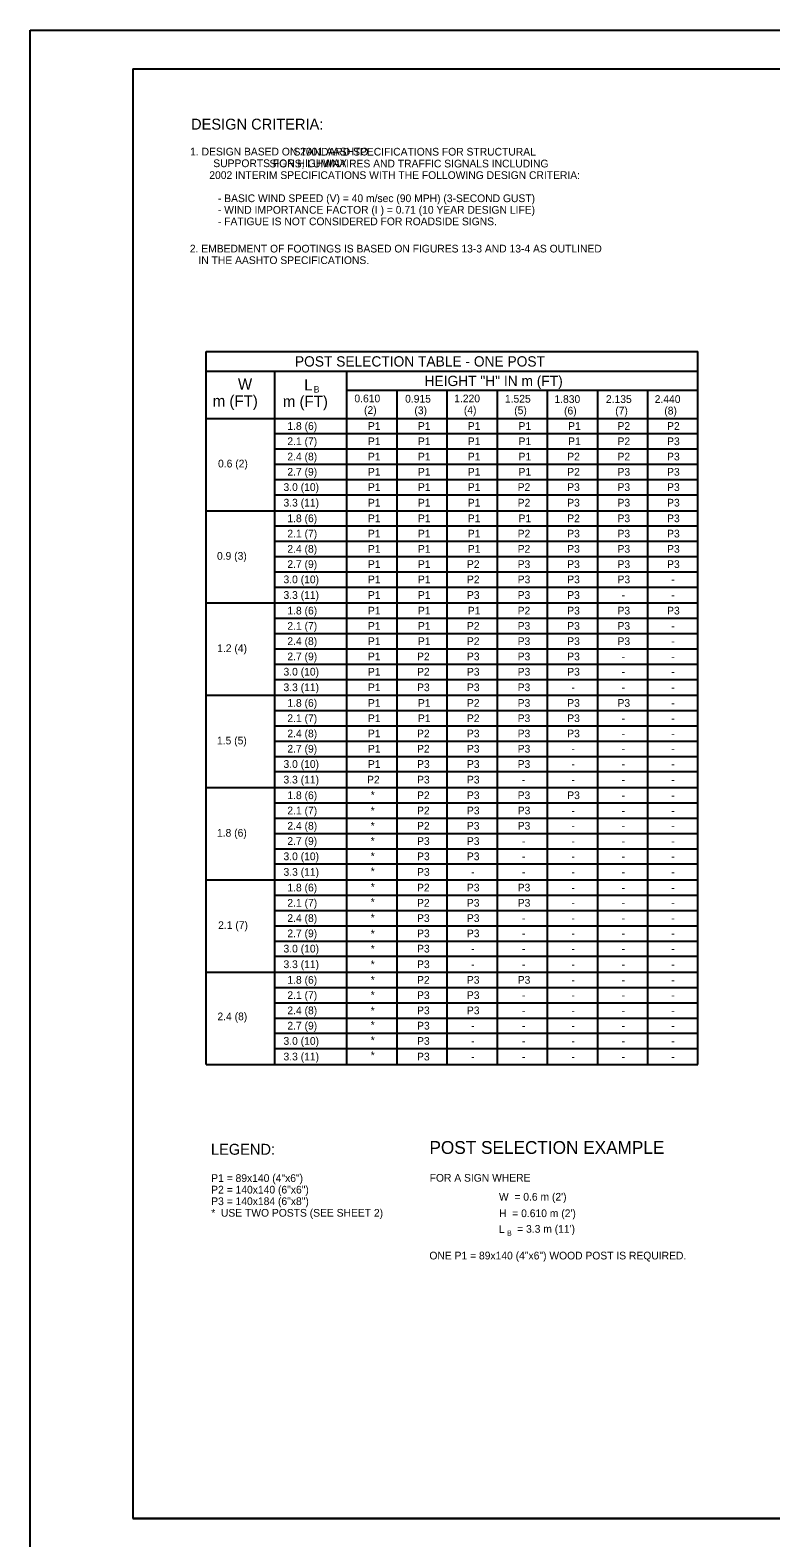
# Model space of a CAD drawing. Extents: x -1958 to 628, y -879 to 309.
# Drawn here: x -1958 to -1670, y -277 to 309 of the extents above; entities that cross this region are included whole.
import ezdxf

# ---------------------------------------------------------------- set-up
doc = ezdxf.new("R2010")
doc.units = 0
for name, color, linetype in [('1', 7, 'Continuous'), ('2', 7, 'Continuous'), ('3', 7, 'Continuous'), ('4', 7, 'Continuous'), ('PLT-BNDY', 7, 'Continuous')]:
    doc.layers.add(name, color=color, linetype=linetype)

msp = doc.modelspace()

# ---------------------------------------------------------------- linework, layer by layer
at = {"layer": '1'}
for p, q in [((-1918.39, 294.44), (-1132.39, 294.44)), ((-1918.39, 294.44), (-1918.39, -269.56)), ((-1889.94, 158.42), (-1889.94, 184.44)), ((-1889.94, 184.44), (-1698.58, 184.44)), ((-1698.58, -92.95), (-1698.58, 184.44)), ((-1889.94, 176.76), (-1835.13, 176.76)), ((-1863.14, -92.95), (-1863.14, 176.76)), ((-1835.13, -92.95), (-1835.13, 176.76)), ((-1835.13, 176.76), (-1698.58, 176.76)), ((-1815.62, 158.42), (-1815.62, 169.42)), ((-1796.12, 158.42), (-1796.12, 169.42)), ((-1776.61, 158.42), (-1776.61, 169.42)), ((-1757.1, 158.42), (-1757.1, 169.42)), ((-1737.59, 158.42), (-1737.59, 169.42)), ((-1718.09, 158.42), (-1718.09, 169.42)), ((-1889.94, 158.42), (-1698.58, 158.42)), ((-1132.39, -269.56), (-1918.39, -269.56)), ((-1918.39, -269.56), (-1332.39, -269.56))]:
    msp.add_line(p, q, dxfattribs=at)
at = {"layer": '2'}
for p, q in [((-1835.13, 169.42), (-1698.58, 169.42)), ((-1889.94, -92.95), (-1889.94, 158.42)), ((-1815.62, -92.95), (-1815.62, 158.42)), ((-1796.12, -92.95), (-1796.12, 158.42)), ((-1776.61, -92.95), (-1776.61, 158.42)), ((-1757.1, -92.95), (-1757.1, 158.42)), ((-1737.59, -92.95), (-1737.59, 158.42)), ((-1718.09, -92.95), (-1718.09, 158.42)), ((-1863.14, 152.48), (-1698.58, 152.48)), ((-1863.14, 146.54), (-1698.58, 146.54)), ((-1863.14, 140.6), (-1698.58, 140.6)), ((-1863.14, 134.66), (-1698.58, 134.66)), ((-1863.14, 128.72), (-1698.58, 128.72)), ((-1889.94, 122.51), (-1698.58, 122.51)), ((-1863.14, 116.57), (-1698.58, 116.57)), ((-1863.14, 110.63), (-1698.58, 110.63)), ((-1863.14, 104.69), (-1698.58, 104.69)), ((-1863.14, 98.75), (-1698.58, 98.75)), ((-1863.14, 92.81), (-1698.58, 92.81)), ((-1889.94, 86.6), (-1698.58, 86.6)), ((-1863.14, 80.66), (-1698.58, 80.66)), ((-1863.14, 74.72), (-1698.58, 74.72)), ((-1863.14, 68.78), (-1698.58, 68.78)), ((-1863.14, 62.84), (-1698.58, 62.84)), ((-1863.14, 56.9), (-1698.58, 56.9)), ((-1889.94, 50.69), (-1698.58, 50.69)), ((-1863.14, 44.75), (-1698.58, 44.75)), ((-1863.14, 38.81), (-1698.58, 38.81)), ((-1863.14, 32.87), (-1698.58, 32.87)), ((-1863.14, 26.93), (-1698.58, 26.93)), ((-1863.14, 20.99), (-1698.58, 20.99)), ((-1889.94, 14.78), (-1698.58, 14.78)), ((-1863.14, 8.84), (-1698.58, 8.84)), ((-1863.14, 2.9), (-1698.58, 2.9)), ((-1863.14, -3.04), (-1698.58, -3.04)), ((-1863.14, -8.98), (-1698.58, -8.98)), ((-1863.14, -14.92), (-1698.58, -14.92)), ((-1889.94, -21.13), (-1698.58, -21.13)), ((-1863.14, -27.07), (-1698.58, -27.07)), ((-1863.14, -33.01), (-1698.58, -33.01)), ((-1863.14, -38.95), (-1698.58, -38.95)), ((-1863.14, -44.89), (-1698.58, -44.89)), ((-1863.14, -50.83), (-1698.58, -50.83)), ((-1889.94, -57.04), (-1698.58, -57.04)), ((-1863.14, -62.98), (-1698.58, -62.98)), ((-1863.14, -68.92), (-1698.58, -68.92)), ((-1863.14, -74.86), (-1698.58, -74.86)), ((-1863.14, -80.8), (-1698.58, -80.8)), ((-1863.14, -86.74), (-1698.58, -86.74)), ((-1889.94, -92.95), (-1698.58, -92.95))]:
    msp.add_line(p, q, dxfattribs=at)
at = {"layer": 'PLT-BNDY'}
msp.add_lwpolyline([(-1958.39, 309.44), (-1117.39, 309.44), (-1117.39, -284.56), (-1958.39, -284.56)], close=True, dxfattribs=at)

# ---------------------------------------------------------------- texts
at = {"layer": '1'}
for s, height, p in [('1. DESIGN BASED ON 2001 AASHTO ', 3, (-1896.14, 260.69)), ('SUPPORTS FOR HIGHWAY ', 3, (-1887.13, 256.15)), ('                      SIGNS, LUMINAIRES AND TRAFFIC SIGNALS INCLUDING', 3, (-1889.8, 256.04)), ('                            STANDARD SPECIFICATIONS FOR STRUCTURAL', 3, (-1887.13, 260.65)), (' 2002 INTERIM SPECIFICATIONS WITH THE FOLLOWING DESIGN CRITERIA:', 3, (-1889.8, 251.54)), ('    - BASIC WIND SPEED (V) = 40 m/sec (90 MPH) (3-SECOND GUST)', 3, (-1889.8, 242.54)), ('    - WIND IMPORTANCE FACTOR (I ) = 0.71 (10 YEAR DESIGN LIFE)', 3, (-1889.8, 238.04)), ('    - FATIGUE IS NOT CONSIDERED FOR ROADSIDE SIGNS.', 3, (-1889.8, 233.54)), ('r', 2, (-1796.87, 238.06)), ('2. EMBEDMENT OF FOOTINGS IS BASED ON FIGURES 13-3 AND 13-4 AS OUTLINED', 3, (-1896.27, 222.95)), ('   IN THE AASHTO SPECIFICATIONS.', 3, (-1896.27, 218.45)), ('POST SELECTION TABLE - ONE POST', 4.003, (-1855.37, 178.58)), ('W', 4.37, (-1877.54, 169.57)), ('L', 4.3, (-1851.75, 169.29)), ('B', 2.5, (-1848.04, 168.46)), ('HEIGHT "H" IN m (FT)', 4.003, (-1804.94, 170.99)), ('m (FT)', 4.375, (-1887.36, 163)), ('m (FT)', 4.375, (-1860.09, 162.83)), ('0.610', 3, (-1832.23, 164.66)), ('0.915', 3, (-1812.51, 164.55)), ('1.220', 3, (-1793.4, 164.66)), ('1.525', 3, (-1773.68, 164.55)), ('1.830', 3, (-1754.42, 164.42)), ('2.135', 3, (-1734.38, 164.42)), ('2.440', 3, (-1715.41, 164.42)), ('(2)', 3, (-1828.49, 160.16)), ('(3)', 3, (-1808.9, 160.05)), ('(4)', 3, (-1789.65, 160.16)), ('(5)', 3, (-1770.06, 160.05)), ('(6)', 3, (-1750.67, 159.92)), ('(7)', 3, (-1730.76, 159.92)), ('(8)', 3, (-1711.67, 159.92)), ('FOR A SIGN WHERE ', 3, (-1802.96, -138.51)), ("W  = 0.6 m (2')", 3, (-1776, -145.89)), ("H  = 0.610 m (2')", 3, (-1775.95, -152.31)), ('L', 3, (-1776, -158.47)), ('B', 2, (-1772.86, -159.52)), (" = 3.3 m (11')", 3, (-1770.02, -158.38)), ('ONE P1 = 89x140 (4"x6") WOOD POST IS REQUIRED.', 3, (-1803.06, -168.76))]:
    msp.add_text(s, height=height, dxfattribs=at).set_placement(p)
at = {"layer": '2'}
for s, height, p in [('DESIGN CRITERIA:', 4.25, (-1895.78, 270.74)), ('1.8 (6)', 3, (-1858.32, 153.95)), ('P1', 3, (-1826.97, 153.95)), ('P1', 3, (-1807.52, 153.95)), ('P1', 3, (-1788.11, 153.95)), ('P1', 3, (-1768.38, 153.95)), ('P1', 3, (-1749.08, 153.95)), ('P2', 3, (-1729.87, 153.95)), ('P2', 3, (-1710.58, 153.95)), ('2.1 (7)', 3, (-1858.32, 148.01)), ('P1', 3, (-1826.97, 148.01)), ('P1', 3, (-1807.52, 148.01)), ('P1', 3, (-1788.11, 148.01)), ('P1', 3, (-1768.38, 148.01)), ('P1', 3, (-1749.08, 148.01)), ('P2', 3, (-1729.87, 148.01)), ('P3', 3, (-1710.58, 148.01)), ('0.6 (2)', 3, (-1885.29, 139.33)), ('2.4 (8)', 3, (-1858.32, 142.07)), ('P1', 3, (-1826.97, 142.07)), ('P1', 3, (-1807.52, 142.07)), ('P1', 3, (-1788.11, 142.07)), ('P1', 3, (-1768.38, 142.07)), ('P2', 3, (-1749.43, 142.07)), ('P2', 3, (-1729.87, 142.07)), ('P3', 3, (-1710.58, 142.07)), ('2.7 (9)', 3, (-1858.32, 136.13)), ('P1', 3, (-1826.97, 136.13)), ('P1', 3, (-1807.52, 136.13)), ('P1', 3, (-1788.11, 136.13)), ('P1', 3, (-1768.38, 136.13)), ('P2', 3, (-1749.43, 136.13)), ('P3', 3, (-1729.87, 136.13)), ('P3', 3, (-1710.58, 136.13)), ('3.0 (10)', 3, (-1859.82, 130.19)), ('P1', 3, (-1826.97, 130.19)), ('P1', 3, (-1807.52, 130.19)), ('P1', 3, (-1788.11, 130.19)), ('P2', 3, (-1768.72, 130.19)), ('P3', 3, (-1749.43, 130.19)), ('P3', 3, (-1729.87, 130.19)), ('P3', 3, (-1710.58, 130.19)), ('3.3 (11)', 3, (-1859.82, 124.12)), ('P1', 3, (-1826.97, 124.12)), ('P1', 3, (-1807.52, 124.12)), ('P1', 3, (-1788.11, 124.12)), ('P2', 3, (-1768.72, 124.12)), ('P3', 3, (-1749.43, 124.12)), ('P3', 3, (-1729.87, 124.12)), ('P3', 3, (-1710.58, 124.12)), ('1.8 (6)', 3, (-1858.32, 118.04)), ('P1', 3, (-1826.97, 118.04)), ('P1', 3, (-1807.52, 118.04)), ('P1', 3, (-1788.11, 118.04)), ('P1', 3, (-1768.38, 118.04)), ('P2', 3, (-1749.43, 118.04)), ('P3', 3, (-1729.87, 118.04)), ('P3', 3, (-1710.58, 118.04)), ('2.1 (7)', 3, (-1858.32, 112.1)), ('P1', 3, (-1826.97, 112.1)), ('P1', 3, (-1807.52, 112.1)), ('P1', 3, (-1788.11, 112.1)), ('P2', 3, (-1768.72, 112.1)), ('P3', 3, (-1749.43, 112.1)), ('P3', 3, (-1729.87, 112.1)), ('P3', 3, (-1710.58, 112.1)), ('0.9 (3)', 3, (-1885.7, 103.42)), ('2.4 (8)', 3, (-1858.32, 106.16)), ('P1', 3, (-1826.97, 106.16)), ('P1', 3, (-1807.52, 106.16)), ('P1', 3, (-1788.11, 106.16)), ('P2', 3, (-1768.72, 106.16)), ('P3', 3, (-1749.43, 106.16)), ('P3', 3, (-1729.87, 106.16)), ('P3', 3, (-1710.58, 106.16)), ('2.7 (9)', 3, (-1858.32, 100.22)), ('P1', 3, (-1826.97, 100.22)), ('P1', 3, (-1807.52, 100.22)), ('P2', 3, (-1788.45, 100.22)), ('P3', 3, (-1768.72, 100.22)), ('P3', 3, (-1749.43, 100.22)), ('P3', 3, (-1729.87, 100.22)), ('P3', 3, (-1710.58, 100.22)), ('3.0 (10)', 3, (-1859.82, 94.28)), ('P1', 3, (-1826.97, 94.28)), ('P1', 3, (-1807.52, 94.28)), ('P2', 3, (-1788.45, 94.28)), ('P3', 3, (-1768.72, 94.28)), ('P3', 3, (-1749.43, 94.28)), ('P3', 3, (-1729.87, 94.28)), ('-', 3, (-1708.96, 94.28)), ('3.3 (11)', 3, (-1859.82, 88.21)), ('P1', 3, (-1826.97, 88.21)), ('P1', 3, (-1807.52, 88.21)), ('P3', 3, (-1788.45, 88.21)), ('P3', 3, (-1768.72, 88.21)), ('P3', 3, (-1749.43, 88.21)), ('-', 3, (-1728.25, 88.21)), ('-', 3, (-1708.96, 88.21)), ('1.8 (6)', 3, (-1858.32, 82.13)), ('P1', 3, (-1826.97, 82.13)), ('P1', 3, (-1807.52, 82.13)), ('P1', 3, (-1788.11, 82.13)), ('P2', 3, (-1768.72, 82.13)), ('P3', 3, (-1749.43, 82.13)), ('P3', 3, (-1729.87, 82.13)), ('P3', 3, (-1710.58, 82.13)), ('2.1 (7)', 3, (-1858.32, 76.19)), ('P1', 3, (-1826.97, 76.19)), ('P1', 3, (-1807.52, 76.19)), ('P2', 3, (-1788.45, 76.19)), ('P3', 3, (-1768.72, 76.19)), ('P3', 3, (-1749.43, 76.19)), ('P3', 3, (-1729.87, 76.19)), ('-', 3, (-1708.96, 76.19)), ('1.2 (4)', 3, (-1885.61, 67.51)), ('2.4 (8)', 3, (-1858.32, 70.25)), ('P1', 3, (-1826.97, 70.25)), ('P1', 3, (-1807.52, 70.25)), ('P2', 3, (-1788.45, 70.25)), ('P3', 3, (-1768.72, 70.25)), ('P3', 3, (-1749.43, 70.25)), ('P3', 3, (-1729.87, 70.25)), ('-', 3, (-1708.96, 70.25)), ('2.7 (9)', 3, (-1858.32, 64.31)), ('P1', 3, (-1826.97, 64.31)), ('P2', 3, (-1807.86, 64.31)), ('P3', 3, (-1788.45, 64.31)), ('P3', 3, (-1768.72, 64.31)), ('P3', 3, (-1749.43, 64.31)), ('-', 3, (-1728.25, 64.31)), ('-', 3, (-1708.96, 64.31)), ('3.0 (10)', 3, (-1859.82, 58.37)), ('P1', 3, (-1826.97, 58.37)), ('P2', 3, (-1807.86, 58.37)), ('P3', 3, (-1788.45, 58.37)), ('P3', 3, (-1768.72, 58.37)), ('P3', 3, (-1749.43, 58.37)), ('-', 3, (-1728.25, 58.37)), ('-', 3, (-1708.96, 58.37)), ('3.3 (11)', 3, (-1859.82, 52.3)), ('P1', 3, (-1826.97, 52.3)), ('P3', 3, (-1807.86, 52.3)), ('P3', 3, (-1788.45, 52.3)), ('P3', 3, (-1768.72, 52.3)), ('-', 3, (-1747.81, 52.3)), ('-', 3, (-1728.25, 52.3)), ('-', 3, (-1708.96, 52.3)), ('1.8 (6)', 3, (-1858.32, 46.22)), ('P1', 3, (-1826.97, 46.22)), ('P1', 3, (-1807.52, 46.22)), ('P2', 3, (-1788.45, 46.22)), ('P3', 3, (-1768.72, 46.22)), ('P3', 3, (-1749.43, 46.22)), ('P3', 3, (-1729.87, 46.22)), ('-', 3, (-1708.96, 46.22)), ('2.1 (7)', 3, (-1858.32, 40.28)), ('P1', 3, (-1826.97, 40.28)), ('P1', 3, (-1807.52, 40.28)), ('P2', 3, (-1788.45, 40.28)), ('P3', 3, (-1768.72, 40.28)), ('P3', 3, (-1749.43, 40.28)), ('-', 3, (-1728.25, 40.28)), ('-', 3, (-1708.96, 40.28)), ('2.4 (8)', 3, (-1858.32, 34.34)), ('P1', 3, (-1826.97, 34.34)), ('P2', 3, (-1807.86, 34.34)), ('P3', 3, (-1788.45, 34.34)), ('P3', 3, (-1768.72, 34.34)), ('P3', 3, (-1749.43, 34.34)), ('-', 3, (-1728.25, 34.34)), ('-', 3, (-1708.96, 34.34)), ('1.5 (5)', 3, (-1885.7, 31.6)), ('2.7 (9)', 3, (-1858.32, 28.4)), ('P1', 3, (-1826.97, 28.4)), ('P2', 3, (-1807.86, 28.4)), ('P3', 3, (-1788.45, 28.4)), ('P3', 3, (-1768.72, 28.4)), ('-', 3, (-1747.81, 28.4)), ('-', 3, (-1728.25, 28.4)), ('-', 3, (-1708.96, 28.4)), ('3.0 (10)', 3, (-1859.82, 22.46)), ('P1', 3, (-1826.97, 22.46)), ('P3', 3, (-1807.86, 22.46)), ('P3', 3, (-1788.45, 22.46)), ('P3', 3, (-1768.72, 22.46)), ('-', 3, (-1747.81, 22.46)), ('-', 3, (-1728.25, 22.46)), ('-', 3, (-1708.96, 22.46)), ('3.3 (11)', 3, (-1859.82, 16.39)), ('P2', 3, (-1827.32, 16.39)), ('P3', 3, (-1807.86, 16.39)), ('P3', 3, (-1788.45, 16.39)), ('-', 3, (-1767.11, 16.39)), ('-', 3, (-1747.81, 16.39)), ('-', 3, (-1728.25, 16.39)), ('-', 3, (-1708.96, 16.39)), ('1.8 (6)', 3, (-1858.32, 10.31)), ('*', 3, (-1825.88, 10.4)), ('P2', 3, (-1807.86, 10.31)), ('P3', 3, (-1788.45, 10.31)), ('P3', 3, (-1768.72, 10.31)), ('P3', 3, (-1749.43, 10.31)), ('2.1 (7)', 3, (-1858.32, 4.37)), ('*', 3, (-1825.88, 4.34)), ('P2', 3, (-1807.86, 4.37)), ('P3', 3, (-1788.45, 4.37)), ('P3', 3, (-1768.7, 4.37)), ('-', 3, (-1728.25, 10.31)), ('-', 3, (-1708.96, 10.31)), ('2.4 (8)', 3, (-1858.32, -1.57)), ('*', 3, (-1825.88, -1.56)), ('P2', 3, (-1807.86, -1.57)), ('P3', 3, (-1788.47, -1.57)), ('P3', 3, (-1768.7, -1.57)), ('-', 3, (-1747.81, 4.37)), ('-', 3, (-1728.25, 4.37)), ('-', 3, (-1708.96, 4.37)), ('1.8 (6)', 3, (-1885.7, -4.31)), ('2.7 (9)', 3, (-1858.32, -7.51)), ('*', 3, (-1825.88, -7.46)), ('P3', 3, (-1807.86, -7.51)), ('P3', 3, (-1788.47, -7.51)), ('-', 3, (-1747.81, -1.57)), ('-', 3, (-1728.25, -1.57)), ('-', 3, (-1708.96, -1.57)), ('3.0 (10)', 3, (-1859.82, -13.45)), ('*', 3, (-1825.88, -13.36)), ('P3', 3, (-1807.86, -13.45)), ('P3', 3, (-1788.47, -13.45)), ('-', 3, (-1767.08, -7.51)), ('-', 3, (-1747.81, -7.51)), ('-', 3, (-1728.25, -7.51)), ('-', 3, (-1708.96, -7.51)), ('3.3 (11)', 3, (-1859.82, -19.52)), ('*', 3, (-1825.88, -19.27)), ('P3', 3, (-1807.86, -19.52)), ('-', 3, (-1767.08, -13.45)), ('-', 3, (-1747.81, -13.45)), ('-', 3, (-1728.25, -13.45)), ('-', 3, (-1708.96, -13.45)), ('1.8 (6)', 3, (-1858.32, -25.6)), ('*', 3, (-1825.88, -25.32)), ('P2', 3, (-1807.86, -25.6)), ('P3', 3, (-1788.47, -25.6)), ('-', 3, (-1786.85, -19.52)), ('P3', 3, (-1768.7, -25.6)), ('-', 3, (-1767.08, -19.52)), ('-', 3, (-1747.81, -19.52)), ('-', 3, (-1728.25, -19.52)), ('-', 3, (-1708.96, -19.52)), ('2.1 (7)', 3, (-1858.32, -31.54)), ('*', 3, (-1825.88, -31.22)), ('P2', 3, (-1807.86, -31.54)), ('P3', 3, (-1788.47, -31.54)), ('P3', 3, (-1768.7, -31.54)), ('-', 3, (-1747.81, -25.6)), ('-', 3, (-1728.25, -25.6)), ('-', 3, (-1708.96, -25.6)), ('2.4 (8)', 3, (-1858.32, -37.48)), ('*', 3, (-1825.88, -37.28)), ('P3', 3, (-1807.86, -37.48)), ('P3', 3, (-1788.47, -37.48)), ('-', 3, (-1747.81, -31.54)), ('-', 3, (-1728.25, -31.54)), ('-', 3, (-1708.96, -31.54)), ('2.1 (7)', 3, (-1885.25, -40.22)), ('2.7 (9)', 3, (-1858.32, -43.42)), ('*', 3, (-1825.88, -43.48)), ('P3', 3, (-1807.86, -43.42)), ('P3', 3, (-1788.47, -43.42)), ('-', 3, (-1767.08, -37.48)), ('-', 3, (-1747.81, -37.48)), ('-', 3, (-1728.25, -37.48)), ('-', 3, (-1708.96, -37.48)), ('3.0 (10)', 3, (-1859.82, -49.36)), ('*', 3, (-1825.88, -49.38)), ('P3', 3, (-1807.86, -49.36)), ('-', 3, (-1767.08, -43.42)), ('-', 3, (-1747.81, -43.42)), ('-', 3, (-1728.25, -43.42)), ('-', 3, (-1708.96, -43.42)), ('3.3 (11)', 3, (-1859.82, -55.43)), ('*', 3, (-1825.88, -55.44)), ('P3', 3, (-1807.86, -55.43)), ('-', 3, (-1786.85, -49.36)), ('-', 3, (-1767.08, -49.36)), ('-', 3, (-1747.81, -49.36)), ('-', 3, (-1728.25, -49.36)), ('-', 3, (-1708.96, -49.36)), ('1.8 (6)', 3, (-1858.32, -61.51)), ('*', 3, (-1825.88, -61.49)), ('P2', 3, (-1807.86, -61.51)), ('P3', 3, (-1788.47, -61.51)), ('-', 3, (-1786.85, -55.43)), ('P3', 3, (-1768.7, -61.51)), ('-', 3, (-1767.08, -55.43)), ('-', 3, (-1747.81, -55.43)), ('-', 3, (-1728.25, -55.43)), ('-', 3, (-1708.96, -55.43)), ('2.1 (7)', 3, (-1858.32, -67.45)), ('*', 3, (-1825.88, -67.39)), ('P3', 3, (-1807.86, -67.45)), ('P3', 3, (-1788.47, -67.45)), ('-', 3, (-1747.81, -61.51)), ('-', 3, (-1728.25, -61.51)), ('-', 3, (-1708.96, -61.51)), ('2.4 (8)', 3, (-1858.32, -73.39)), ('P3', 3, (-1807.86, -73.39)), ('P3', 3, (-1788.47, -73.39)), ('-', 3, (-1767.08, -67.45)), ('-', 3, (-1747.81, -67.45)), ('-', 3, (-1728.25, -67.45)), ('-', 3, (-1708.96, -67.45)), ('2.4 (8)', 3, (-1885.52, -75.72)), ('2.7 (9)', 3, (-1858.32, -79.33)), ('*', 3, (-1825.88, -73.45)), ('*', 3, (-1825.88, -79.05)), ('-', 3, (-1767.08, -73.39)), ('-', 3, (-1747.81, -73.39)), ('-', 3, (-1728.25, -73.39)), ('-', 3, (-1708.96, -73.39)), ('*', 3, (-1825.88, -84.95)), ('P3', 3, (-1807.86, -79.33)), ('-', 3, (-1786.85, -79.33)), ('-', 3, (-1767.08, -79.33)), ('-', 3, (-1747.81, -79.33)), ('-', 3, (-1728.25, -79.33)), ('-', 3, (-1708.96, -79.33)), ('3.0 (10)', 3, (-1859.82, -85.27)), ('*', 3, (-1825.88, -90.85)), ('P3', 3, (-1807.86, -85.27)), ('-', 3, (-1786.85, -85.27)), ('-', 3, (-1767.08, -85.27)), ('-', 3, (-1747.81, -85.27)), ('-', 3, (-1728.25, -85.27)), ('-', 3, (-1708.96, -85.27)), ('3.3 (11)', 3, (-1859.82, -91.34)), ('P3', 3, (-1807.86, -91.34)), ('-', 3, (-1786.85, -91.34)), ('-', 3, (-1767.08, -91.34)), ('-', 3, (-1747.81, -91.34)), ('-', 3, (-1728.25, -91.34)), ('-', 3, (-1708.96, -91.34)), ('POST SELECTION EXAMPLE', 5, (-1803.04, -127.71))]:
    msp.add_text(s, height=height, dxfattribs=at).set_placement(p)
at = {"layer": '3'}
msp.add_text('LEGEND:', height=4.25, dxfattribs=at).set_placement((-1888.05, -128.04))
at = {"layer": '4'}
for s, p in [('P1 = 89x140 (4"x6")', (-1887.95, -138.62)), ('P2 = 140x140 (6"x6")', (-1887.95, -143.12)), ('P3 = 140x184 (6"x8")', (-1887.95, -147.62)), ('*  USE TWO POSTS (SEE SHEET 2)', (-1887.95, -152.12))]:
    msp.add_text(s, height=3, dxfattribs=at).set_placement(p)

doc.saveas('drawing.dxf')
